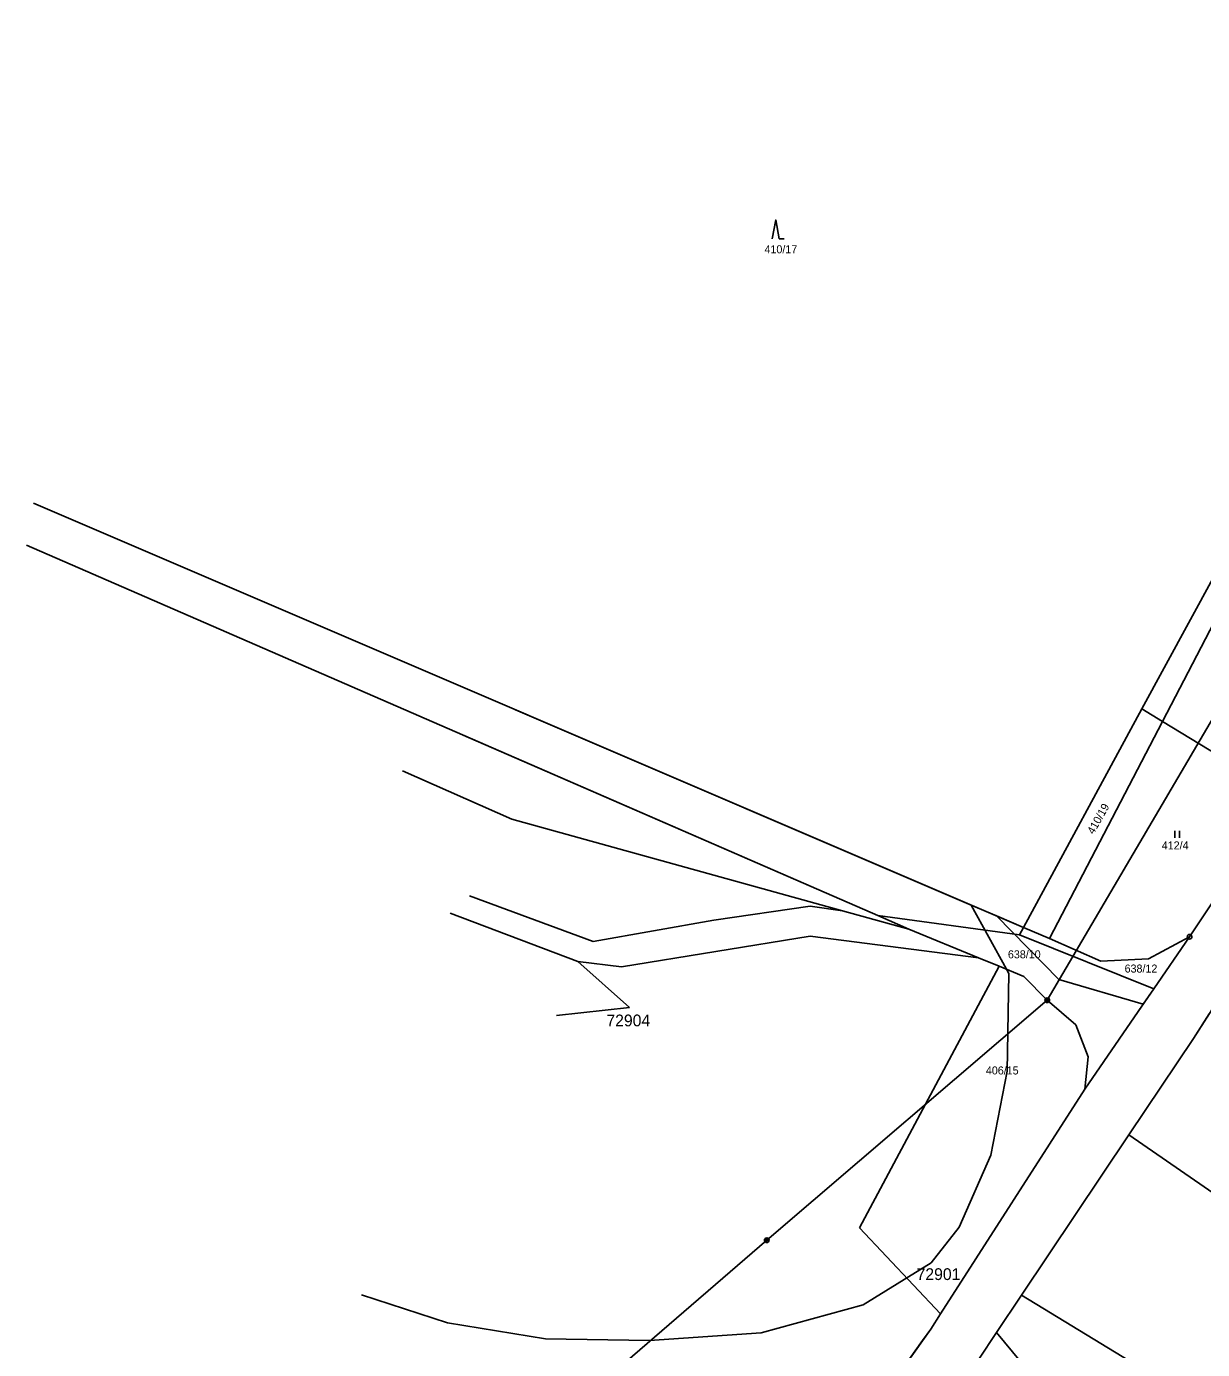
# Model space of a CAD drawing. Extents: x -743888 to -742027, y -1128394 to -1126768.
# Drawn here: x -743883.3 to -743633.6, y -1127319.9 to -1127038.8 of the extents above; entities that cross this region are included whole.
import ezdxf

# ---------------------------------------------------------------- set-up
doc = ezdxf.new("R2010")
doc.units = 0
for name, color, linetype in [('Vrstva 1', 7, 'Continuous'), ('Vrstva 12', 7, 'Continuous'), ('Vrstva 18', 7, 'Continuous'), ('Vrstva 24', 7, 'Continuous'), ('Vrstva 25', 7, 'Continuous'), ('Vrstva 26', 7, 'Continuous'), ('Vrstva 52', 7, 'Continuous'), ('Vrstva 53', 7, 'Continuous'), ('Vrstva 6', 7, 'Continuous')]:
    doc.layers.add(name, color=color, linetype=linetype)

msp = doc.modelspace()

# ---------------------------------------------------------------- linework, layer by layer
at = {"layer": 'Vrstva 1'}
for points in [[(-743642.12, -1127186.45), (-743597.45, -1127100.54)], [(-743881.84, -1127140.1), (-743671.64, -1127230.23)], [(-743883.35, -1127148.98), (-743702.59, -1127227.7)], [(-743666.12, -1127232.6), (-743642.12, -1127186.45)], [(-743636.37, -1127232.18), (-743616.38, -1127202.08)], [(-743780.26, -1127207.21), (-743710.09, -1127226.67)], [(-743710.09, -1127226.67), (-743695.97, -1127230.58)], [(-743702.59, -1127227.7), (-743695.97, -1127230.58)], [(-743695.97, -1127230.58), (-743681.2, -1127236.66)], [(-743671.64, -1127230.23), (-743666.12, -1127232.6)], [(-743666.12, -1127232.6), (-743655.22, -1127237.38)], [(-743645.09, -1127236.9), (-743636.37, -1127232.18)], [(-743643.98, -1127243.27), (-743636.37, -1127232.18)], [(-743681.2, -1127236.66), (-743676.81, -1127238.46)], [(-743676.81, -1127238.46), (-743671.57, -1127240.62)], [(-743655.22, -1127237.38), (-743645.09, -1127236.9)], [(-743671.57, -1127240.62), (-743666.59, -1127245.69)], [(-743647.27, -1127248.07), (-743643.98, -1127243.27)], [(-743635.53, -1127253.78), (-743629.87, -1127244.98)], [(-743666.59, -1127245.69), (-743660.49, -1127250.92)], [(-743658.6, -1127264.57), (-743647.27, -1127248.07)], [(-743660.49, -1127250.92), (-743657.88, -1127257.69)], [(-743649.24, -1127274.28), (-743635.53, -1127253.78)], [(-743658.6, -1127264.57), (-743657.88, -1127257.69)], [(-743689.23, -1127312.32), (-743658.6, -1127264.57)], [(-743672.05, -1127308.38), (-743649.24, -1127274.28)], [(-743677.33, -1127316.28), (-743672.05, -1127308.38)], [(-743691.32, -1127315.58), (-743689.23, -1127312.32)], [(-743701.89, -1127330.35), (-743691.32, -1127315.58)], [(-743681.13, -1127321.96), (-743677.33, -1127316.28)]]:
    msp.add_lwpolyline(points, dxfattribs=at)
at = {"layer": 'Vrstva 12'}
for points in [[(-743666.59, -1127245.69), (-743624.66, -1127174.21)], [(-743726.15, -1127296.67), (-743666.59, -1127245.69)], [(-743780.05, -1127343.28), (-743726.15, -1127296.67)]]:
    msp.add_lwpolyline(points, dxfattribs=at)
at = {"layer": 'Vrstva 24'}
msp.add_line((-743636.42, -1127232.18), (-743636.32, -1127232.18), dxfattribs=at)
msp.add_circle((-743636.37, -1127232.18), 0.499, dxfattribs=at)
at = {"layer": 'Vrstva 25'}
for p, q in [((-743639.52, -1127209.67), (-743639.52, -1127211.17)), ((-743638.52, -1127211.17), (-743638.52, -1127209.67))]:
    msp.add_line(p, q, dxfattribs=at)
msp.add_lwpolyline([(-743724.98, -1127083.9), (-743724.23, -1127079.9), (-743723.48, -1127083.9), (-743722.48, -1127083.9)], dxfattribs=at)
at = {"layer": 'Vrstva 26'}
for p, q in [((-743667.05, -1127245.87), (-743666.41, -1127245.23)), ((-743666.79, -1127246.14), (-743666.14, -1127245.49)), ((-743726.61, -1127296.85), (-743725.96, -1127296.21)), ((-743726.35, -1127297.12), (-743725.7, -1127296.47))]:
    msp.add_line(p, q, dxfattribs=at)
for centre in [(-743666.59, -1127245.69), (-743726.15, -1127296.67)]:
    msp.add_circle(centre, 0.5, dxfattribs=at)
at = {"layer": 'Vrstva 52'}
for points in [[(-743677.39, -1127227.76), (-743671.64, -1127230.23), (-743666.12, -1127232.6), (-743642.12, -1127186.45), (-743597.45, -1127100.54), (-743561.27, -1127030.96), (-743560.68, -1127029.82), (-743555.91, -1127020.65)], [(-743646.21, -1127246.53), (-743643.98, -1127243.27), (-743636.37, -1127232.18), (-743616.38, -1127202.08), (-743576.94, -1127142.72), (-743560.72, -1127118.19), (-743522.03, -1127059.68), (-743516.89, -1127051.64), (-743512.05, -1127044.08)], [(-743779.52, -1127183.97), (-743682.73, -1127225.48)], [(-743790.59, -1127189.38), (-743702.59, -1127227.7), (-743695.97, -1127230.58), (-743710.09, -1127226.67), (-743780.26, -1127207.21), (-743803.51, -1127196.91)], [(-743812.19, -1127308.25), (-743793.94, -1127314.25), (-743773.13, -1127317.63), (-743751.06, -1127318), (-743727.31, -1127316.38), (-743705.69, -1127310.38), (-743691.25, -1127301.5), (-743685.31, -1127293.88), (-743678.56, -1127278.63), (-743675.13, -1127260.75), (-743674.75, -1127240), (-743675.24, -1127239.11), (-743682.73, -1127225.48)], [(-743682.73, -1127225.48), (-743677.39, -1127227.76)], [(-743677.39, -1127227.76), (-743664.13, -1127241.25), (-743646.21, -1127246.53)], [(-743792.03, -1127331.05), (-743785.55, -1127332.01), (-743770.32, -1127335.04), (-743736.1, -1127333.22), (-743706.94, -1127335.88), (-743704.43, -1127331.53), (-743702.67, -1127331.44), (-743701.89, -1127330.35), (-743693.05, -1127318), (-743691.32, -1127315.58), (-743689.23, -1127312.32), (-743658.6, -1127264.57), (-743647.27, -1127248.07), (-743646.21, -1127246.53)], [(-743678.44, -1127390.67), (-743671.53, -1127378.48), (-743658.11, -1127354.78), (-743660.69, -1127352.59), (-743659, -1127349), (-743658.7, -1127346.57), (-743664.22, -1127341.91), (-743673.62, -1127333.98), (-743679.84, -1127327.83), (-743680.26, -1127326.97), (-743682.93, -1127324.62), (-743682.05, -1127323.29), (-743681.13, -1127321.96), (-743677.33, -1127316.28), (-743672.05, -1127308.38), (-743649.24, -1127274.28), (-743635.53, -1127253.78), (-743632.18, -1127248.58)]]:
    msp.add_lwpolyline(points, dxfattribs=at)
at = {"layer": 'Vrstva 6'}
for points in [[(-743646.48, -1127183.8), (-743600.41, -1127099.12)], [(-743671.64, -1127230.23), (-743646.48, -1127183.8)], [(-743646.48, -1127183.8), (-743642.12, -1127186.45)], [(-743642.12, -1127186.45), (-743616.38, -1127202.08)], [(-743789.24, -1127223.49), (-743763.04, -1127233.2)], [(-743793.36, -1127227.19), (-743766.29, -1127237.43)], [(-743737.38, -1127228.65), (-743716.91, -1127225.73)], [(-743716.91, -1127225.73), (-743710.09, -1127226.67)], [(-743702.59, -1127227.7), (-743672.5, -1127231.82)], [(-743763.04, -1127233.2), (-743737.38, -1127228.65)], [(-743672.5, -1127231.82), (-743671.64, -1127230.23)], [(-743757.03, -1127238.57), (-743716.91, -1127232.07)], [(-743716.91, -1127232.07), (-743681.2, -1127236.66)], [(-743672.5, -1127231.82), (-743643.98, -1127243.27)], [(-743766.29, -1127237.43), (-743755.28, -1127247.25)], [(-743766.29, -1127237.43), (-743757.03, -1127238.57)], [(-743706.45, -1127294.03), (-743676.81, -1127238.46)], [(-743770.82, -1127248.95), (-743755.28, -1127247.25)], [(-743649.24, -1127274.28), (-743622.26, -1127292.92)], [(-743706.45, -1127294.03), (-743689.23, -1127312.32)], [(-743672.05, -1127308.38), (-743638.39, -1127328.87)], [(-743677.33, -1127316.28), (-743670.54, -1127324.52)]]:
    msp.add_lwpolyline(points, dxfattribs=at)

# ---------------------------------------------------------------- texts
at = {"layer": 'Vrstva 18'}
for s, p in [('410/17', (-743726.63, -1127086.98)), ('412/4', (-743642.27, -1127213.63)), ('638/10', (-743674.94, -1127236.78)), ('638/12', (-743650.16, -1127239.8)), ('406/15', (-743679.62, -1127261.45))]:
    msp.add_text(s, height=1.7, dxfattribs=at).set_placement(p)
msp.add_text('410/19', height=1.7, rotation=60.5543, dxfattribs=at).set_placement((-743656.74, -1127210.56))
at = {"layer": 'Vrstva 53'}
for s, p in [('72904', (-743760.2, -1127251.23)), ('72901', (-743694.33, -1127305.13))]:
    msp.add_text(s, height=2.5, dxfattribs=at).set_placement(p)

doc.saveas('drawing.dxf')
